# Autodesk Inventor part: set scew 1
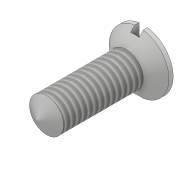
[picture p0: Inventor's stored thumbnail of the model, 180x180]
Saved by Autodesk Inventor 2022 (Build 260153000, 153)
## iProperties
Created: 2016-06
Part Number: set scew 1
Material: Generic
Document SubType Name: Modeling
Designer: CADCIM
Density: 1 g/cm^3
Appearance: Default
Mass: 0.577668 g
Surface Area: 5.12671 cm^2
Volume: 0.577668 cm^3
Author: CADCIM
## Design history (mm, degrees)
sketch "Sketch1"
  geometry: C1 r 3 at (0, 0); 1 further point
  constraints: 1 centre point, 1 coincident
  dimensions: "d0" = 6 diameter of C1
extrude "Extrusion1" new body sketch "Sketch1" distance "d1" = 14; taper "d2" = 0 deg
sketch "Sketch2"
  geometry: L1 (14, -3)-(14, 3) reference; L2 (14, 0)-(14, -3); L3 (14, -3)-(17, -6); L4 (17, -6)-(17, 0); L5 (17, 0)-(14, 0); 1 further point
  constraints: 8 end point, 2 vertical, 1 midpoint, 1 perpendicular
  dimensions: "d4" = 3 distance of L2.start L2.end; "d5" = 6 distance of L4.end L3.end; "d6" = 3 distance from line of L1.start L4
revolve "Revolution1" sketch "Sketch2" stored, may be unused: angle "d7" = 90 deg
sketch "Sketch3"
  geometry: C1 r 5.25 at (0, 0); 1 further point
  constraints: 1 centre point, 1 coincident
  dimensions: "d8" = 10.5 diameter of C1
extrude "Extrusion2" sketch "Sketch3" distance "d9" = 26.75; taper "d10" = 0 deg
sketch "Sketch4"
  geometry: L1 (-0.75, 8.347)-(0.75, 8.347); L2 (0.75, 8.347)-(0.75, -8.125); L3 (0.75, -8.125)-(-0.75, -8.125); L4 (-0.75, -8.125)-(-0.75, 8.347); L5 (0, 0)-(0, 6.165)
  constraints: 10 end point, 3 parallel, 1 horizontal, 1 perpendicular, 1 other
  dimensions: "d11" = 1.5 distance of L1.start L1.end
extrude "Extrusion3" cut sketch "Sketch4" distance "d12" = 1.5; taper "d13" = 0 deg
sketch "Sketch5"
  geometry: L1 (0, 0)-(0, 3); L2 (0, 3)-(-1.732, 0); L3 (-1.732, 0)-(0, 0); L4 (0, 3)-(0, -3) reference; 1 further point
  constraints: 6 end point, 2 midpoint, 1 perpendicular, 1 point on line, 1 vertical
  dimensions: "d21" = 60 deg angle of L2 L3; "d22" = 3 distance of L1.start L1.end
thread "Thread2" dims "d19" = 10, "d20" = 0
revolve "Revolution3" stored, may be unused: angle "d23" = 90 deg
body "Solid1"
